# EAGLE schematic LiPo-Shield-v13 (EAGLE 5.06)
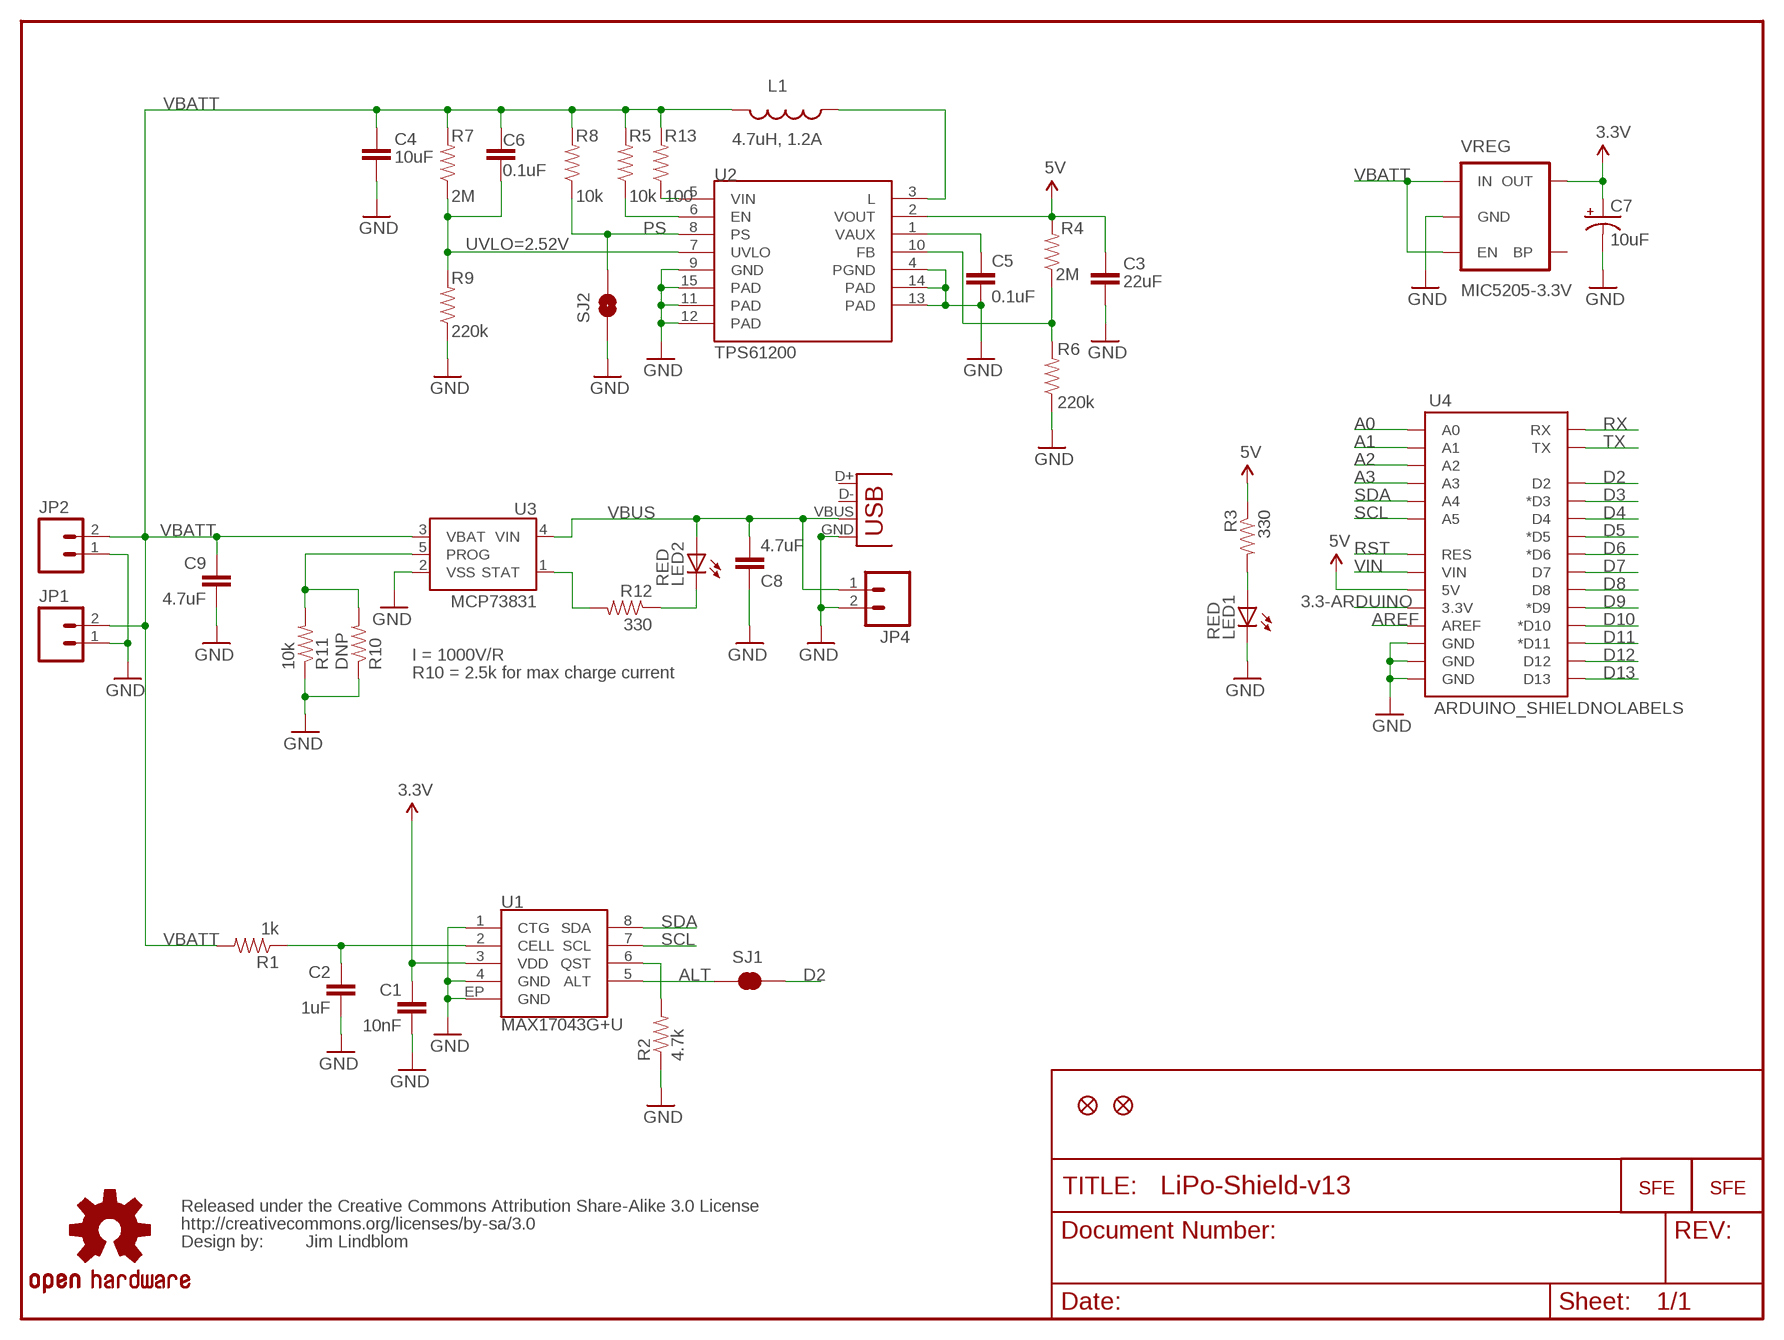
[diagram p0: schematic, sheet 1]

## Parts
$$U$1  CREATIVE_COMMONS  [CREATIVE_COMMONS]
C1  10nF  CAP0402-CAP  [0402-CAP]
C2  1uF  CAP0402-CAP  [0402-CAP]
C3  22uF  CAP0805  [0805]
C4  10uF  CAP1206  [1206]
C5  0.1uF  CAP0402-CAP  [0402-CAP]
C6  0.1uF  CAP0402-CAP  [0402-CAP]
C7  10uF  CAP_POL1206  [EIA3216]
C8  4.7uF  CAP0402-CAP  [0402-CAP]
C9  4.7uF  CAP0402-CAP  [0402-CAP]
JP1  M021X02_NO_SILK  [1X02_NO_SILK]
JP2  M02-JST-2MM-SMT  [JST-2-SMD]
JP3  LOGO-SFENW2  [SFE-NEW-WEB]
JP4  M021X02_NO_SILK  [1X02_NO_SILK]
JP5  FIDUCIAL1X2.5  [FIDUCIAL-1X2.5]
JP6  FIDUCIAL1X2.5  [FIDUCIAL-1X2.5]
JP100  LOGO-SFESK  [SFE-LOGO-FLAME]
L1  4.7uH, 1.2A  INDUCTOR.  [CDRH2D09]
LED1  RED  LED0603  [LED-0603]
LED2  RED  LED0603  [LED-0603]
R1  1k  RESISTOR0402-RES  [0402-RES]
R2  4.7k  RESISTOR0402-RES  [0402-RES]
R3  330  RESISTOR0402-RES  [0402-RES]
R4  2M  RESISTOR0402-RES  [0402-RES]
R5  10k  RESISTOR0402-RES  [0402-RES]
R6  220k  RESISTOR0402-RES  [0402-RES]
R7  2M  RESISTOR0402-RES  [0402-RES]
R8  10k  RESISTOR0402-RES  [0402-RES]
R9  220k  RESISTOR0402-RES  [0402-RES]
R10  DNP  RESISTORPTH-1/6W  [1/6W-RES]
R11  10k  RESISTOR0402-RES  [0402-RES]
R12  330  RESISTOR0402-RES  [0402-RES]
R13  100  RESISTOR0402-RES  [0402-RES]
SJ1  SOLDERJUMPERTRACE  [SJ_2S-TRACE]
SJ2  PS  SOLDERJUMPERNO  [SJ_2S-NO]
U1  MAX17043G+U  MAX1704X  [TDFN-8]
U2  TPS61200  [QFN-10_PAD]
U3  MCP73831  [SOT23-5]
U4  ARDUINO_SHIELDNOLABELS  [DUEMILANOVE_SHIELD_NOLABELS]
U$100  OSHW-LOGOM  [OSHW-LOGO-M]
VREG  MIC5205-3.3V  V_REG_LDOSMD  [SOT23-5]
X1  USBSMD  [USB-MINIB]

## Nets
3.3-ARDUINO: U4.3.3V
3.3V: C1.1 C7.A(+) U1.3(VDD) VREG.5(OUT)
5V: C3.1 R3.1 R4.2 U2.2(VOUT) U4.5V
A0: U4.A0
A1: U4.A1
A2: U4.A2
A3: U4.A3
ALT: SJ1.1 U1.5(ALT)
AREF: U4.AREF
CELL: C2.1 R1.1 U1.2(CELL)
D2: SJ1.2 U4.D2
D3: U4.D3(*D3)
D4: U4.D4
D5: U4.D5(*D5)
D6: U4.D6(*D6)
D7: U4.D7
D8: U4.D8
D9: U4.D9(*D9)
D10: U4.D10(*D10)
D11: U4.D11(*D11)
D12: U4.D12
D13: U4.D13
EN: R5.1 U2.6(EN)
FB: R4.1 R6.2 U2.10(FB)
GND: C1.2 C2.2 C3.2 C4.2 C5.2 C7.C(-) C8.1 C9.2 JP1.1 JP2.1 JP4.2 LED1.C R2.1 R6.1 R9.1 R10.1 R11.1 SJ2.1 U1.1(CTG) U1.4(GND) U1.EP(GND) U2.4(PGND) U2.9(GND) U2.11(PAD) U2.12(PAD) U2.13(PAD) U2.14(PAD) U2.15(PAD) U3.2(VSS) U4.GND@0(GND) U4.GND@1(GND) U4.GND@2(GND) VREG.2(GND) X1.GND
N$1: LED1.A R3.2
N$3: L1.P$1 U2.3(L)
N$4: C5.1 U2.1(VAUX)
N$5: LED2.C R12.1
PROG: R10.2 R11.2 U3.5(PROG)
PS: R8.1 SJ2.2 U2.8(PS)
QST: R2.2 U1.6(QST)
RST: U4.RES
RX: U4.RX
SCL: U1.7(SCL) U4.A5
SDA: U1.8(SDA) U4.A4
STAT: R12.2 U3.1(STAT)
TX: U4.TX
UVLO: C6.2 R7.1 R9.2 U2.7(UVLO)
VBATT: C4.1 C6.1 C9.1 JP1.2 JP2.2 L1.P$2 R1.2 R5.2 R7.2 R8.2 R13.2 U3.3(VBAT) VREG.1(IN) VREG.3(EN)
VBUS: C8.2 JP4.1 LED2.A U3.4(VIN) X1.VBUS
VIN: U4.VIN
VIN-L: R13.1 U2.5(VIN)
Unconnected: VREG.4(BP) X1.D+ X1.D-

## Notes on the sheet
- UVLO=2.52V
- I = 1000V/R
- R10 = 2.5k for max charge current
- Jim Lindblom

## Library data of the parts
$$U$1 = SparkFun:CREATIVE_COMMONS
C1 C2 C5 C6 C8 C9 = SparkFun:CAP: Capacitor
C3 C4 = CH_passive:CAP: Capacitor
C7 = SparkFun:CAP_POL: Capacitor Polarized
JP1 JP2 JP4 = SparkFun:M02: Header 2
JP3 JP100 = SparkFun:LOGO-SFE: Spark Fun Electronics PCB Logo
JP5 JP6 = abes:FIDUCIAL: Fiducial Alignment Points
L1 = SparkFun:INDUCTOR: Inductors
LED1 LED2 = SparkFun:LED: LEDs
R1-R13 = SparkFun:RESISTOR: Resistor
SJ1 SJ2 = SparkFun:SOLDERJUMPER: Solder Jumper
U1 = SparkFun:MAX1704X: MAX17043/MAX17044: Battery Fuel Guage (43 is 1cell, 44 is 2cell)
U2 = SparkFun:TPS61200: DC to DC Booster
U3 = SparkFun:MCP73831: Microchip's MCP73831 Miniature single cell, fully integrated Li-Ion, Li-polymer charge management controller http://ww1.microchip.com/downloads/en/DeviceDoc/21984a.pdf
U4 = SparkFun:ARDUINO_SHIELD
U$100 = SparkFun:OSHW-LOGO: Open Source Hardware Logo This logo indicates the piece of hardware it is found on incorporates a OSHW license and/or adheres to the definition of open source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
VREG = SparkFun:V_REG_LDO: Voltage Regulator LDO Standard 150mA LDO voltage regulator in SOT-23 layout. Micrel part MIC5205. BP (by-pass) pin is used to lower output noise with 470pF cap.
X1 = SparkFun:USB: USB Connectors USB-B-PTH is fully proven SKU : PRT-00139 USB-miniB is fully proven SKU : PRT-00587 USB-A-PCB is untested. USB-A-H is throughly reviewed, but untested. Spark Fun Electronics SKU : PRT-00437 USB-B-SMT is throughly reviewed, but untested. Needs silkscreen touching up. USB-A-S has not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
